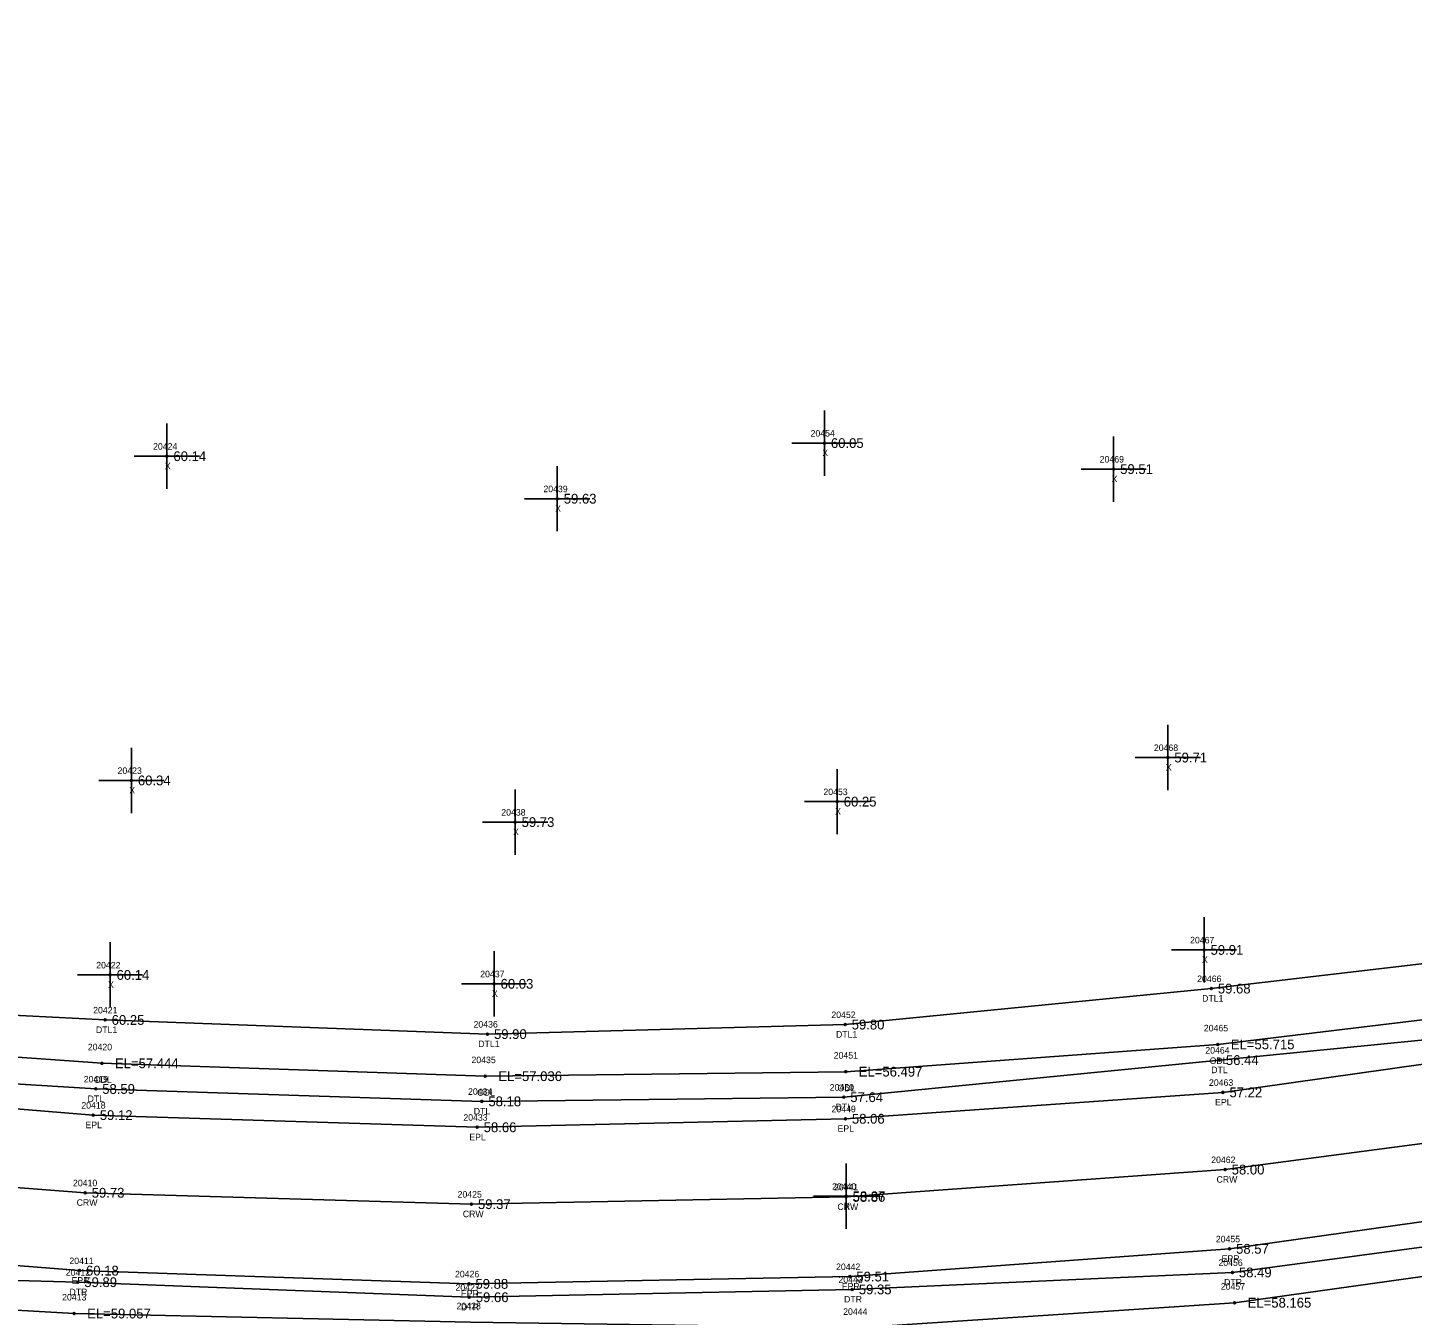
# Model space of a CAD drawing. Extents: x 2420351 to 2422725, y 845330 to 846558.
# Drawn here: x 2421166.9 to 2421379.3, y 845661.3 to 845858.7 of the extents above; entities that cross this region are included whole.
import ezdxf

# ---------------------------------------------------------------- set-up
doc = ezdxf.new("R2010")
doc.units = 0
for name, color, linetype in [('RD_DTM_BkLn1', 7, 'Continuous'), ('RD_EX_H2O', 7, 'Continuous'), ('RD_EX_H2O_txCode', 7, 'Continuous'), ('RD_EX_Misc', 7, 'Continuous'), ('RD_EX_Misc_txCode', 7, 'Continuous'), ('RD_EX_Road', 7, 'Continuous'), ('RD_EX_Road_txCode', 7, 'Continuous'), ('RD_EX_TX_H2O_ELEV', 7, 'Continuous'), ('RD_EX_TX_Misc_ELEV', 7, 'Continuous'), ('RD_EX_TX_Road_ELEV', 7, 'Continuous'), ('RD_HC_Survey_ELEV', 7, 'Continuous'), ('RD_HC_Survey_txCode', 7, 'Continuous'), ('RD_SMD_Locator', 7, 'Continuous')]:
    doc.layers.add(name, color=color, linetype=linetype)

msp = doc.modelspace()

# ---------------------------------------------------------------- linework, layer by layer
at = {"layer": 'RD_DTM_BkLn1'}
msp.add_lwpolyline([(2420378.71, 845690.53), (2420439.5, 845704.09), (2420489.95, 845712.49), (2420551.89, 845719.42), (2420551.95, 845719.57), (2420607.12, 845722.67), (2420682.92, 845723.04), (2420749.65, 845719.68), (2420796.31, 845715.7), (2420900.74, 845705.33), (2421018.16, 845694.11), (2421114.61, 845684.8), (2421175.74, 845680.1), (2421234.97, 845678.35), (2421292.42, 845679.46), (2421350.56, 845683.65), (2421414.53, 845692.12), (2421472.54, 845703.63), (2421533.08, 845718.31), (2421555.4, 845725.02), (2421609.81, 845741.71), (2421666.58, 845762.88), (2421744.67, 845798.22)], dxfattribs=at)
at = {"layer": 'RD_EX_H2O'}
for points in [[(2420975.55, 846190.58), (2420976.37, 846105.11), (2420974.31, 845997.82), (2420976.03, 845896.74), (2420974.59, 845794.18), (2420975.37, 845743.63), (2420984.12, 845720.99), (2420999.91, 845711.18), (2421116.7, 845699.77), (2421177.35, 845696.01), (2421236.57, 845694.11), (2421292.07, 845694.75), (2421349.67, 845700.43), (2421411.57, 845706.56), (2421470.63, 845718.76), (2421529.96, 845732.93), (2421551.14, 845737.51), (2421602.97, 845753.33), (2421656.85, 845776.48), (2421724.45, 845805.15), (2421739.21, 845812.56)], [(2420980.17, 846190.47), (2420980.93, 846104.85), (2420980.02, 845997.99), (2420979.17, 845896.92), (2420978.72, 845794), (2420978.72, 845743.89), (2420987.58, 845724.3), (2421000.53, 845717.13), (2421117.24, 845704.33), (2421178.3, 845699.94), (2421237.1, 845697.97), (2421292.37, 845698.66), (2421349.43, 845702.84), (2421410.88, 845710.25), (2421469.94, 845721.7), (2421529.19, 845736.54), (2421550.26, 845742.27), (2421602, 845757.38), (2421655.89, 845778.44), (2421721.41, 845810.89), (2421742.22, 845823.45)], [(2420984.17, 846190.38), (2420983.45, 846105.14), (2420982.87, 845998.03), (2420982.41, 845897.21), (2420981.52, 845793.93), (2420982.23, 845744.07), (2420990.87, 845727.81), (2421002.71, 845721.72), (2421118.19, 845709.67), (2421178.8, 845706.59), (2421237.43, 845704.42), (2421292.29, 845705.88), (2421348.44, 845711.4), (2421408.11, 845718.43)], [(2420681.02, 845707.72), (2420749.24, 845704.74), (2420794.5, 845700.07), (2420899.98, 845690.96), (2421017.54, 845678.31), (2421112.89, 845668.07), (2421174.6, 845666.39), (2421234.64, 845664.08), (2421293.38, 845665.28), (2421351.67, 845667.88), (2421422.34, 845677.35), (2421426.88, 845673.47), (2421424.22, 845667.22)], [(2420680.88, 845704.69), (2420749.16, 845701.08), (2420794.33, 845696.81), (2420899.79, 845687.85), (2421017.53, 845674.81), (2421112.48, 845665.13), (2421174.04, 845661.58), (2421234.82, 845660.24), (2421294.09, 845659.38), (2421352.01, 845663.24), (2421417.66, 845672.42), (2421424.72, 845673.17)]]:
    msp.add_lwpolyline(points, dxfattribs=at)
at = {"layer": 'RD_EX_Misc'}
for p, q in [((2421289.1, 845790.03), (2421289.1, 845800.03)), ((2421188.27, 845788.02), (2421188.27, 845798.02)), ((2421333.46, 845786.04), (2421333.46, 845796.04)), ((2421284.1, 845795.03), (2421294.1, 845795.03)), ((2421183.27, 845793.02), (2421193.27, 845793.02)), ((2421248.13, 845781.5), (2421248.13, 845791.5)), ((2421328.46, 845791.04), (2421338.46, 845791.04)), ((2421243.13, 845786.5), (2421253.13, 845786.5)), ((2421341.77, 845741.82), (2421341.77, 845751.82)), ((2421182.82, 845738.31), (2421182.82, 845748.31)), ((2421291.07, 845735.06), (2421291.07, 845745.06)), ((2421336.77, 845746.82), (2421346.77, 845746.82)), ((2421177.82, 845743.31), (2421187.82, 845743.31)), ((2421241.67, 845731.92), (2421241.67, 845741.92)), ((2421286.07, 845740.06), (2421296.07, 845740.06)), ((2421236.67, 845736.92), (2421246.67, 845736.92)), ((2421347.32, 845712.33), (2421347.32, 845722.33)), ((2421179.55, 845708.49), (2421179.55, 845718.49)), ((2421238.44, 845707.13), (2421238.44, 845717.13)), ((2421342.32, 845717.33), (2421352.32, 845717.33)), ((2421174.55, 845713.49), (2421184.55, 845713.49)), ((2421233.44, 845712.13), (2421243.44, 845712.13)), ((2421292.44, 845674.56), (2421292.44, 845684.56)), ((2421287.44, 845679.56), (2421297.44, 845679.56))]:
    msp.add_line(p, q, dxfattribs=at)
at = {"layer": 'RD_EX_Road'}
for points in [[(2420388.28, 845680.39), (2420441.29, 845692.04), (2420492.62, 845700.7), (2420553.92, 845707.41), (2420607.69, 845710.85), (2420682.38, 845711.26), (2420749.44, 845707.27), (2420795.12, 845703.44), (2420900.28, 845693.42), (2421017.17, 845682.19), (2421113.9, 845672.97), (2421174.87, 845668.16), (2421234.59, 845666.13), (2421293, 845667.25), (2421351.24, 845671.5), (2421419.82, 845681.17), (2421463.19, 845688.63), (2421558.82, 845713.18), (2421614.57, 845730.45), (2421670.73, 845751.42), (2421735.61, 845780.5), (2421750.75, 845787.87), (2421744.67, 845798.22), (2421739.21, 845808.11)], [(2420376.35, 845701.93), (2420403.68, 845709.11), (2420436.45, 845715.41), (2420465.85, 845720.8), (2420487.58, 845724.76), (2420551.29, 845731.53), (2420607.05, 845734.89), (2420658.72, 845735.59), (2420682.86, 845735.47), (2420736.67, 845732.56), (2420795.4, 845727.65), (2420889.7, 845718.98), (2420911.08, 845716.87), (2420953.91, 845713.71), (2420998.34, 845708.25), (2421018.47, 845706.55), (2421116.02, 845696.98), (2421176.98, 845692), (2421235.85, 845690.14), (2421292.32, 845691.44), (2421350.22, 845695.49), (2421412.35, 845704.28)]]:
    msp.add_lwpolyline(points, dxfattribs=at)
at = {"layer": 'RD_SMD_Locator'}
for centre in [(2421289.1, 845795.03), (2421188.27, 845793.02), (2421333.46, 845791.04), (2421248.13, 845786.5), (2421341.77, 845746.82), (2421182.82, 845743.31), (2421291.07, 845740.06), (2421241.67, 845736.92), (2421347.32, 845717.33), (2421179.55, 845713.49), (2421238.44, 845712.13), (2421348.44, 845711.4), (2421178.8, 845706.59), (2421237.43, 845704.42), (2421292.29, 845705.88), (2421349.43, 845702.84), (2421349.67, 845700.43), (2421178.3, 845699.94), (2421237.1, 845697.97), (2421292.37, 845698.66), (2421177.35, 845696.01), (2421236.57, 845694.11), (2421292.07, 845694.75), (2421350.22, 845695.49), (2421176.98, 845692), (2421235.85, 845690.14), (2421292.32, 845691.44), (2421350.56, 845683.65), (2421175.74, 845680.1), (2421292.42, 845679.46), (2421292.44, 845679.56), (2421234.97, 845678.35), (2421351.24, 845671.5), (2421174.87, 845668.16), (2421174.6, 845666.39), (2421234.59, 845666.13), (2421293, 845667.25), (2421351.67, 845667.88), (2421234.64, 845664.08), (2421293.38, 845665.28), (2421352.01, 845663.24), (2421174.04, 845661.58)]:
    msp.add_circle(centre, 0.15, dxfattribs=at)

# ---------------------------------------------------------------- texts
at = {"layer": 'RD_EX_H2O_txCode'}
for s, p in [('20466', (2421346.27, 845712.4)), ('DTL1', (2421347.03, 845709.4)), ('20421', (2421176.96, 845707.59)), ('20452', (2421290.17, 845706.88)), ('DTL1', (2421177.39, 845704.59)), ('20436', (2421235.29, 845705.42)), ('DTL1', (2421290.88, 845703.88)), ('20465', (2421347.29, 845704.84)), ('20420', (2421176.14, 845701.94)), ('DTL1', (2421236.02, 845702.42)), ('20464', (2421347.52, 845701.43)), ('20435', (2421234.98, 845699.97)), ('20451', (2421290.53, 845700.66)), ('ODL', (2421348.18, 845699.84)), ('20419', (2421175.52, 845697.01)), ('DTL', (2421348.42, 845698.43)), ('ODL', (2421177.06, 845696.94)), ('20434', (2421234.45, 845695.11)), ('ODL', (2421235.85, 845694.97)), ('20450', (2421289.92, 845695.75)), ('ODL', (2421291.12, 845695.66)), ('DTL', (2421176.11, 845694.01)), ('DTL', (2421235.33, 845692.11)), ('DTL', (2421290.83, 845692.75)), ('20412', (2421172.76, 845667.39)), ('20456', (2421349.53, 845668.88)), ('20443', (2421291.26, 845666.28)), ('20457', (2421349.89, 845665.24)), ('DTR', (2421350.4, 845665.88)), ('20413', (2421172.2, 845663.58)), ('DTR', (2421173.33, 845664.39)), ('20427', (2421232.53, 845665.08)), ('DTR', (2421292.11, 845663.28)), ('20428', (2421232.7, 845662.24)), ('DTR', (2421233.38, 845662.08)), ('20444', (2421291.98, 845661.38))]:
    msp.add_text(s, height=1, dxfattribs=at).set_placement(p)
at = {"layer": 'RD_EX_Misc_txCode'}
for s, p in [('20454', (2421286.98, 845796.03)), ('20424', (2421186.15, 845794.02)), ('X', (2421288.78, 845793.03)), ('X', (2421187.95, 845791.02)), ('20469', (2421331.32, 845792.04)), ('X', (2421333.14, 845789.04)), ('20439', (2421246.01, 845787.5)), ('X', (2421247.82, 845784.5)), ('20468', (2421339.63, 845747.82)), ('20423', (2421180.7, 845744.31)), ('X', (2421341.46, 845744.82)), ('X', (2421182.5, 845741.31)), ('20453', (2421288.95, 845741.06)), ('20438', (2421239.55, 845737.92)), ('X', (2421290.75, 845738.06)), ('X', (2421241.35, 845734.92)), ('20467', (2421345.18, 845718.33)), ('20422', (2421177.43, 845714.49)), ('X', (2421347, 845715.33)), ('20437', (2421236.32, 845713.13)), ('X', (2421179.24, 845711.49)), ('X', (2421238.12, 845710.13)), ('20440', (2421290.28, 845680.56)), ('X', (2421292.12, 845677.56))]:
    msp.add_text(s, height=1, dxfattribs=at).set_placement(p)
at = {"layer": 'RD_EX_Road_txCode'}
for s, p in [('20463', (2421348.08, 845696.49)), ('20418', (2421175.15, 845693)), ('EPL', (2421349.02, 845693.49)), ('20433', (2421233.73, 845691.14)), ('20449', (2421290.2, 845692.44)), ('EPL', (2421175.78, 845690)), ('EPL', (2421291.11, 845689.44)), ('EPL', (2421234.65, 845688.14)), ('20455', (2421349.13, 845672.5)), ('EPR', (2421350.02, 845669.5)), ('20411', (2421173.32, 845669.16)), ('20442', (2421290.89, 845668.25)), ('EPR', (2421173.64, 845666.16)), ('20426', (2421232.45, 845667.13)), ('EPR', (2421291.77, 845665.25)), ('EPR', (2421233.36, 845664.13))]:
    msp.add_text(s, height=1, dxfattribs=at).set_placement(p)
at = {"layer": 'RD_EX_TX_H2O_ELEV'}
for s, p in [('59.68', (2421349.44, 845710.65)), ('60.25', (2421179.8, 845705.84)), ('59.80', (2421293.29, 845705.13)), ('59.90', (2421238.43, 845703.67)), ('EL=55.715', (2421351.43, 845702.09)), ('EL=57.444', (2421180.3, 845699.19)), ('56.44', (2421350.67, 845699.68)), ('EL=57.036', (2421239.1, 845697.22)), ('EL=56.497', (2421294.37, 845697.91)), ('58.59', (2421178.35, 845695.26)), ('58.18', (2421237.57, 845693.36)), ('57.64', (2421293.07, 845694)), ('58.49', (2421352.67, 845667.13)), ('59.89', (2421175.6, 845665.64)), ('59.66', (2421235.64, 845663.33)), ('59.35', (2421294.38, 845664.53)), ('EL=59.057', (2421176.04, 845660.83)), ('EL=58.165', (2421354.01, 845662.49))]:
    msp.add_text(s, height=1.5, dxfattribs=at).set_placement(p)
at = {"layer": 'RD_EX_TX_Misc_ELEV'}
for s, p in [('60.05', (2421290.1, 845794.28)), ('60.14', (2421189.27, 845792.27)), ('59.51', (2421334.46, 845790.29)), ('59.63', (2421249.13, 845785.75)), ('59.71', (2421342.77, 845746.07)), ('60.34', (2421183.82, 845742.56)), ('60.25', (2421292.07, 845739.31)), ('59.73', (2421242.67, 845736.17)), ('59.91', (2421348.32, 845716.58)), ('60.14', (2421180.55, 845712.74)), ('60.03', (2421239.44, 845711.38)), ('58.87', (2421293.44, 845678.81))]:
    msp.add_text(s, height=1.5, dxfattribs=at).set_placement(p)
at = {"layer": 'RD_EX_TX_Road_ELEV'}
for s, p in [('57.22', (2421351.22, 845694.74)), ('59.12', (2421177.98, 845691.25)), ('58.06', (2421293.32, 845690.69)), ('58.66', (2421236.85, 845689.39)), ('58.57', (2421352.24, 845670.75)), ('60.18', (2421175.87, 845667.41)), ('59.88', (2421235.59, 845665.38)), ('59.51', (2421294, 845666.5))]:
    msp.add_text(s, height=1.5, dxfattribs=at).set_placement(p)
at = {"layer": 'RD_HC_Survey_ELEV'}
for s, p in [('58.00', (2421351.56, 845682.9)), ('59.73', (2421176.74, 845679.35)), ('59.37', (2421235.97, 845677.6)), ('58.86', (2421293.42, 845678.71))]:
    msp.add_text(s, height=1.5, dxfattribs=at).set_placement(p)
at = {"layer": 'RD_HC_Survey_txCode'}
for s, p in [('20462', (2421348.42, 845684.65)), ('20410', (2421173.87, 845681.1)), ('20441', (2421290.58, 845680.46)), ('CRW', (2421349.24, 845681.65)), ('CRW', (2421174.43, 845678.1)), ('20425', (2421232.85, 845679.35)), ('CRW', (2421233.65, 845676.35)), ('CRW', (2421291.1, 845677.46))]:
    msp.add_text(s, height=1, dxfattribs=at).set_placement(p)

doc.saveas('drawing.dxf')
